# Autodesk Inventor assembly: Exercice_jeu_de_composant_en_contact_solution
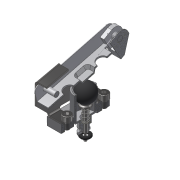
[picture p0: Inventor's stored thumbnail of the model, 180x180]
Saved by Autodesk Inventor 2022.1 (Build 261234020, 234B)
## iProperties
Created: 2018-06
Part Number: Exercice_jeu_de_composant_en_contact_solution
Material: Générique
Document SubType Name: Assembly
Designer: Fabian Perrée
Mass: 316.677 g
Surface Area: 499.858 cm^2
Volume: 83.3782 cm^3
Density: 3.79808 g/cm^3
Author: Fabian Perrée
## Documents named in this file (4)
- C:\Users\fabia\Mon Drive\01_Giup\01_Clients\07_ENI\Manuscrit\Fichiers_exercice\Chapitre_06\Exercice_jeu_de_composant_en_contact\Exercice_jeu_de_composant_en_contact_solution.iam
- C:\Users\fabia\Mon Drive\01_Giup\01_Clients\07_ENI\Manuscrit\Fichiers_exercice\Chapitre_06\Exercice_jeu_de_composant_en_contact\Composants\Ens_levier\Ens_levier.iam
- C:\Users\fabia\Mon Drive\01_Giup\01_Clients\07_ENI\Manuscrit\Fichiers_exercice\Chapitre_06\Exercice_jeu_de_composant_en_contact\Composants\Ens_chapeau\Ens_chapeau.iam
- C:\Users\fabia\Mon Drive\01_Giup\01_Clients\07_ENI\Manuscrit\Fichiers_exercice\Chapitre_06\Exercice_jeu_de_composant_en_contact\Composants\Ens_poussoir\Ens_poussoir.iam
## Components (3 placed, 3 different names)
1. Ens_levier:1 [sub-assembly] — Placage:26, Placage:27, Drive_Me, Placage:30
2. Ens_chapeau:1 [sub-assembly] — Placage:26, Placage:27, Drive_Me, Placage:30, Logement:1
3. Ens_poussoir:1 [sub-assembly] — Logement:1
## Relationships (5: Mate 3, Angle 1, Insert 1)
- Placage:26 [Mate]: Ens_levier:1 ↔ Ens_chapeau:1
- Placage:27 [Mate]: Ens_levier:1 ↔ Ens_chapeau:1
- Drive_Me [Angle]: Ens_levier:1 ↔ Ens_chapeau:1
- Placage:30 [Mate]: Ens_levier:1 ↔ Ens_chapeau:1
- Logement:1 [Insert]: Ens_chapeau:1 ↔ Ens_poussoir:1
